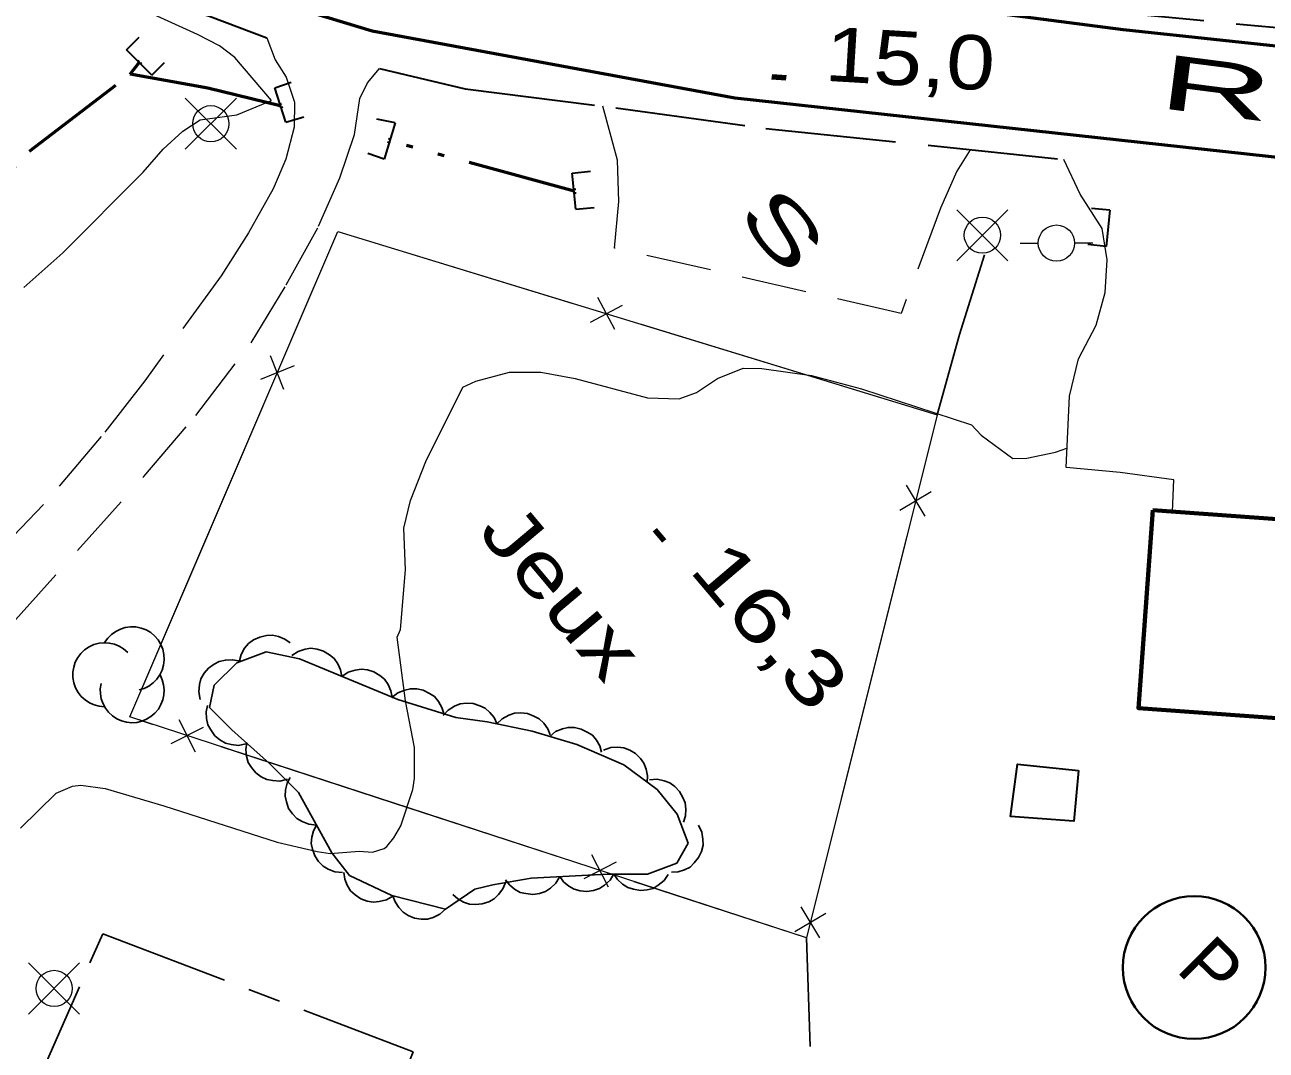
# Model space of a CAD drawing. Extents: x 386081 to 389416, y 5130568 to 5134082.
# Drawn here: x 387512.1 to 387580.7, y 5132255.4 to 5132312.1 of the extents above; entities that cross this region are included whole.
import ezdxf
from ezdxf.enums import TextEntityAlignment as Align

# ---------------------------------------------------------------- set-up
doc = ezdxf.new("R2010")
doc.units = 0
doc.header["$LTSCALE"] = 1.2
for name, pattern in [('DASH_DOUBLE_DOT', [9.2, 5, -1.2, 0.3, -1.2, 0.3, -1.2]), ('DOT_DASHED', [7.7, 5, -1.2, 0.3, -1.2]), ('LONG_DASH_SHORT_DASH', [9.9, 6, -1.2, 1.5, -1.2]), ('LONG_DASHED', [7.5, 6, -1.5]), ('MEDIUM_DASHED', [4.5, 3, -1.5])]:
    doc.linetypes.add(name, pattern=pattern)
for name, color, linetype, lineweight in [('19', 7, 'Continuous', 13), ('2', 7, 'Continuous', 13), ('21', 7, 'LONG_DASHED', 35), ('26', 7, 'Continuous', 35), ('3', 7, 'Continuous', 140), ('31', 7, 'Continuous', 70), ('36', 7, 'Continuous', 13), ('37', 7, 'Continuous', 13), ('38', 7, 'Continuous', 40), ('4', 7, 'DASH_DOUBLE_DOT', 53), ('41', 7, 'DOT_DASHED', 25), ('44', 7, 'Continuous', 25), ('52', 7, 'Continuous', 13), ('56', 7, 'LONG_DASH_SHORT_DASH', 25)]:
    doc.layers.add(name, color=color, linetype=linetype, lineweight=lineweight)

msp = doc.modelspace()

# ---------------------------------------------------------------- linework, layer by layer
at = {"layer": '19', "linetype": 'MEDIUM_DASHED'}
for points in [[(387525.46, 5132311.34), (387525.92, 5132310.13), (387526.53, 5132309.17), (387526.99, 5132307.8), (387526.97, 5132306.42), (387526.5, 5132304.65), (387525.81, 5132303), (387524.45, 5132300.57), (387522.93, 5132298.21), (387518.71, 5132292.41), (387516.31, 5132289.32), (387513.11, 5132285.57), (387509.86, 5132282.19)], [(387511.4, 5132279.01), (387518.66, 5132287.12), (387521.53, 5132290.48), (387524.59, 5132294.51), (387526.53, 5132297.7), (387528.31, 5132300.94), (387529.49, 5132303.61), (387530.29, 5132306.01), (387530.59, 5132307.99), (387531.02, 5132308.86), (387531.67, 5132309.65)]]:
    msp.add_lwpolyline(points, dxfattribs=at)
at = {"layer": '19'}
msp.add_lwpolyline([(387575.49, 5132285.19), (387575.57, 5132286.94), (387572.6, 5132287.34), (387569.61, 5132287.62), (387569.79, 5132291.55), (387570.29, 5132293.62), (387571.27, 5132295.48), (387571.77, 5132297.28), (387571.88, 5132299.08), (387571.61, 5132300.82), (387570.39, 5132302.72), (387569.49, 5132304.63)], dxfattribs=at)
at = {"layer": '2'}
for points in [[(387512.03, 5132297.55), (387514.18, 5132299.47), (387518.63, 5132303.92), (387519.72, 5132305.2), (387520.81, 5132306.2), (387521.77, 5132306.82), (387523.8, 5132307.09), (387525.71, 5132307.88), (387523.69, 5132310.26), (387522.84, 5132310.91), (387521.63, 5132311.54), (387512.31, 5132315.78)], [(387511.85, 5132267.7), (387513.81, 5132269.62), (387514.72, 5132270.01), (387515.18, 5132270.07), (387516.53, 5132269.88), (387519.77, 5132268.93), (387526.03, 5132266.93), (387528.23, 5132266.4), (387528.95, 5132266.3), (387530.56, 5132266.42), (387531.3, 5132266.37), (387531.94, 5132266.57), (387532.09, 5132266.69), (387532.48, 5132267.17), (387532.86, 5132267.82), (387533.52, 5132269.84), (387533.62, 5132270.43), (387533.61, 5132272.15), (387533.11, 5132274.72), (387532.65, 5132278.24), (387532.83, 5132278.66), (387533.12, 5132281.96), (387533.02, 5132284.26), (387533.39, 5132285.8), (387534.23, 5132287.95), (387536.29, 5132292.05), (387537, 5132292.38), (387538.87, 5132292.88), (387540.59, 5132292.88), (387542.48, 5132292.53), (387546.48, 5132291.46), (387548.23, 5132291.41), (387549.19, 5132291.75), (387550.36, 5132292.53), (387551.77, 5132293.11), (387552.81, 5132293.09), (387555.54, 5132292.7), (387558.31, 5132291.97), (387564.39, 5132289.98), (387564.92, 5132289.4), (387566.67, 5132288.12), (387567.44, 5132288.13), (387569.02, 5132288.46), (387569.66, 5132288.69)]]:
    msp.add_lwpolyline(points, dxfattribs=at)
at = {"layer": '21'}
for points in [[(387448.55, 5132347.71), (387450.3, 5132348.4), (387452.56, 5132348.87), (387454.71, 5132349.01), (387456.48, 5132348.48), (387458.74, 5132347.62), (387461.09, 5132346.33), (387475.71, 5132335.51), (387479.64, 5132332.82), (387488.41, 5132327.05), (387497.41, 5132322.26), (387505.92, 5132318.13), (387510.87, 5132316.08), (387516.12, 5132314.38), (387522.29, 5132312.55), (387525.46, 5132311.34)], [(387736.86, 5132291.57), (387733.6, 5132291.99), (387709.58, 5132295.61), (387698.35, 5132296.9), (387691.83, 5132297.26), (387677.28, 5132298.75), (387662.94, 5132300.94), (387653.62, 5132302.21), (387642.37, 5132303.91), (387632.55, 5132305.72), (387621.75, 5132307.01), (387608.95, 5132308.73), (387597.98, 5132310.12), (387586.17, 5132311.43), (387566.07, 5132313.34), (387563.16, 5132314.3), (387562.13, 5132315.42), (387561.79, 5132316.7), (387562.33, 5132318.66), (387563.51, 5132320.54), (387564.77, 5132322.24), (387565.97, 5132323.49)], [(387531.67, 5132309.65), (387536.41, 5132308.53), (387544.73, 5132307.49), (387553.03, 5132306.34), (387569.49, 5132304.63)]]:
    msp.add_lwpolyline(points, dxfattribs=at)
at = {"layer": '21', "linetype": 'Continuous', "lineweight": 53}
for points in [[(387527.13, 5132312.98), (387531.27, 5132311.74), (387551.31, 5132308.03), (387585.48, 5132304.29), (387592.5, 5132303.69), (387599.65, 5132302.96), (387616.75, 5132301.03), (387622.08, 5132300.05), (387628.01, 5132299.22), (387640.73, 5132297.17), (387655.66, 5132295.26), (387659.42, 5132294.51), (387661.63, 5132293.87), (387663.49, 5132292.45), (387665.22, 5132290.58), (387666.62, 5132288.63), (387667.3, 5132286.86), (387667.22, 5132284.79), (387663.68, 5132256.15), (387661.63, 5132241.07)], [(387562.39, 5132313.16), (387572.77, 5132311.8), (387583.77, 5132310.63), (387600.02, 5132308.74), (387614.35, 5132307.05), (387628.29, 5132305.3), (387641.74, 5132303.18), (387670.62, 5132298.94), (387720.03, 5132292.53), (387763.15, 5132287.28), (387788.03, 5132285.2)]]:
    msp.add_lwpolyline(points, dxfattribs=at)
at = {"layer": '26'}
for p, q in [((387517.71, 5132310.68), (387518.41, 5132311.38)), ((387519.11, 5132309.28), (387517.71, 5132310.68)), ((387518.34, 5132310.05), (387518.41, 5132310.12)), ((387518.48, 5132309.91), (387518.34, 5132310.05)), ((387518.48, 5132309.91), (387518.55, 5132309.98)), ((387519.11, 5132309.28), (387519.81, 5132309.98)), ((387525.9, 5132308.59), (387526.8, 5132308.89)), ((387526.5, 5132306.69), (387525.9, 5132308.59)), ((387526.17, 5132307.69), (387526.26, 5132307.72)), ((387526.23, 5132307.5), (387526.17, 5132307.69)), ((387526.23, 5132307.5), (387526.33, 5132307.53)), ((387526.5, 5132306.69), (387527.5, 5132306.99)), ((387532.54, 5132306.65), (387531.54, 5132306.85)), ((387532.54, 5132306.65), (387531.94, 5132304.65)), ((387532.21, 5132305.55), (387532.12, 5132305.58)), ((387532.27, 5132305.75), (387532.17, 5132305.77)), ((387532.27, 5132305.75), (387532.21, 5132305.55)), ((387531.94, 5132304.65), (387531.04, 5132304.95)), ((387542.33, 5132303.88), (387543.33, 5132303.98)), ((387542.53, 5132301.88), (387542.33, 5132303.88)), ((387542.42, 5132302.98), (387542.52, 5132302.99)), ((387542.44, 5132302.78), (387542.42, 5132302.98)), ((387542.44, 5132302.78), (387542.54, 5132302.79)), ((387542.53, 5132301.88), (387543.53, 5132301.98)), ((387572.02, 5132301.83), (387571.02, 5132301.93)), ((387572.02, 5132301.83), (387571.82, 5132299.83)), ((387571.82, 5132299.83), (387570.82, 5132299.93))]:
    msp.add_line(p, q, dxfattribs=at)
at = {"layer": '3'}
for p, q in [((387553.36, 5132309.19), (387554.15, 5132309.14)), ((387546.89, 5132284.17), (387547.4, 5132283.56))]:
    msp.add_line(p, q, dxfattribs=at)
at = {"layer": '31'}
msp.add_lwpolyline([(387574.41, 5132285.26), (387585.85, 5132284.43), (387585.06, 5132273.5), (387573.61, 5132274.33)], close=True, dxfattribs=at)
at = {"layer": '31', "lineweight": 35}
msp.add_lwpolyline([(387570.3, 5132270.88), (387570.03, 5132268.09), (387566.54, 5132268.34), (387566.93, 5132271.23)], close=True, dxfattribs=at)
at = {"layer": '36'}
for p, q in [((387523.77, 5132305.19), (387520.95, 5132308.01)), ((387520.95, 5132305.19), (387523.77, 5132308.01)), ((387566.39, 5132299.03), (387563.57, 5132301.85)), ((387563.57, 5132299.03), (387566.39, 5132301.85)), ((387567.08, 5132300.01), (387568.08, 5132300.01)), ((387571.08, 5132300.01), (387570.08, 5132300.01)), ((387515.11, 5132257.43), (387512.29, 5132260.25)), ((387512.29, 5132257.43), (387515.11, 5132260.25))]:
    msp.add_line(p, q, dxfattribs=at)
for centre in [(387522.364, 5132306.605), (387564.984, 5132300.445), (387569.074, 5132300.01), (387513.704, 5132258.845)]:
    msp.add_circle(centre, 1, dxfattribs=at)
at = {"layer": '37'}
for p, q in [((387532.74, 5132299.62), (387542.3, 5132296.7)), ((387543.33, 5132295.64), (387545.1, 5132296.58)), ((387544.68, 5132295.23), (387543.74, 5132297)), ((387546.13, 5132295.53), (387555.69, 5132292.61)), ((387526.4, 5132291.93), (387525.66, 5132293.79)), ((387526.96, 5132293.23), (387525.1, 5132292.48)), ((387521.31, 5132281.82), (387525.25, 5132291.02)), ((387560.43, 5132285.26), (387562.15, 5132286.29)), ((387560.78, 5132286.64), (387561.81, 5132284.92)), ((387560.81, 5132283.84), (387558.38, 5132274.13)), ((387558.38, 5132274.13), (387555.96, 5132264.43)), ((387521.93, 5132273.26), (387520.15, 5132272.36)), ((387520.59, 5132273.7), (387521.49, 5132271.92)), ((387532.45, 5132269.08), (387522.94, 5132272.19)), ((387541.95, 5132265.98), (387532.45, 5132269.08)), ((387543.4, 5132266.25), (387544.31, 5132264.46)), ((387544.75, 5132265.81), (387542.96, 5132264.9)), ((387555.26, 5132261.63), (387545.75, 5132264.74)), ((387554.62, 5132261.98), (387556.33, 5132263.01)), ((387554.96, 5132263.35), (387555.99, 5132261.63))]:
    msp.add_line(p, q, dxfattribs=at)
msp.add_lwpolyline([(387555.26, 5132261.63), (387517.89, 5132273.84), (387529.37, 5132300.65), (387562.48, 5132290.53)], close=True, dxfattribs=at)
for points in [[(387526.82, 5132294.69), (387529.37, 5132300.65), (387532.74, 5132299.62)], [(387555.69, 5132292.61), (387562.48, 5132290.53), (387561.78, 5132287.72)], [(387519.14, 5132273.43), (387517.89, 5132273.84), (387521.31, 5132281.82)]]:
    msp.add_lwpolyline(points, dxfattribs=at)
at = {"layer": '38'}
msp.add_circle((387576.686, 5132260), 3.941, dxfattribs=at)
at = {"layer": '4'}
msp.add_line((387542.43, 5132302.88), (387532.24, 5132305.65), dxfattribs=at)
for points in [[(387526.2, 5132307.59), (387522.2, 5132308.57), (387517.91, 5132309.34), (387518.41, 5132309.98)], [(387486.04, 5132262.3), (387484.84, 5132263.26), (387481.63, 5132266.45), (387480.38, 5132268.94), (387480.96, 5132271.69), (387484.1, 5132275.76), (387493.5, 5132285.18), (387505.02, 5132297.25), (387512.35, 5132305.09), (387517.91, 5132309.34)]]:
    msp.add_lwpolyline(points, dxfattribs=at)
at = {"layer": '41'}
msp.add_line((387555.26, 5132261.63), (387555.65, 5132250.78), dxfattribs=at)
msp.add_lwpolyline([(387562.48, 5132290.53), (387563.72, 5132294.96), (387565.11, 5132299.37)], dxfattribs=at)
at = {"layer": '44'}
for points in [[(387523.93, 5132276.87), (387524.03, 5132277.28), (387524.23, 5132277.63), (387524.44, 5132277.89), (387524.72, 5132278.09), (387525.06, 5132278.25), (387525.43, 5132278.33), (387525.76, 5132278.36), (387526.1, 5132278.28), (387526.45, 5132278.14), (387526.74, 5132277.93)], [(387526.83, 5132277.23), (387527.18, 5132277.46), (387527.57, 5132277.58), (387527.89, 5132277.63), (387528.24, 5132277.58), (387528.59, 5132277.47), (387528.92, 5132277.27), (387529.17, 5132277.07), (387529.37, 5132276.77), (387529.53, 5132276.44), (387529.6, 5132276.08)], [(387521.77, 5132274.81), (387521.69, 5132275.22), (387521.73, 5132275.63), (387521.81, 5132275.95), (387521.99, 5132276.25), (387522.23, 5132276.53), (387522.54, 5132276.76), (387522.83, 5132276.91), (387523.17, 5132276.98), (387523.54, 5132277), (387523.9, 5132276.93)], [(387529.6, 5132276.08), (387529.95, 5132276.32), (387530.34, 5132276.43), (387530.66, 5132276.48), (387531.01, 5132276.44), (387531.37, 5132276.33), (387531.69, 5132276.12), (387531.95, 5132275.92), (387532.15, 5132275.63), (387532.3, 5132275.29), (387532.37, 5132274.94)], [(387532.36, 5132274.91), (387532.69, 5132275.17), (387533.07, 5132275.32), (387533.39, 5132275.4), (387533.74, 5132275.39), (387534.1, 5132275.31), (387534.44, 5132275.14), (387534.72, 5132274.96), (387534.94, 5132274.69), (387535.12, 5132274.36), (387535.23, 5132274.02)], [(387524.3, 5132272.35), (387523.89, 5132272.27), (387523.49, 5132272.31), (387523.17, 5132272.39), (387522.86, 5132272.57), (387522.58, 5132272.8), (387522.36, 5132273.12), (387522.2, 5132273.4), (387522.13, 5132273.75), (387522.11, 5132274.12), (387522.18, 5132274.47)], [(387535.2, 5132273.91), (387535.48, 5132274.22), (387535.83, 5132274.43), (387536.14, 5132274.56), (387536.49, 5132274.6), (387536.86, 5132274.58), (387537.22, 5132274.46), (387537.52, 5132274.33), (387537.78, 5132274.09), (387538.01, 5132273.81), (387538.17, 5132273.48)], [(387538.17, 5132273.45), (387538.46, 5132273.74), (387538.83, 5132273.93), (387539.14, 5132274.05), (387539.49, 5132274.07), (387539.85, 5132274.03), (387540.21, 5132273.89), (387540.5, 5132273.74), (387540.75, 5132273.49), (387540.97, 5132273.19), (387541.11, 5132272.86)], [(387541.08, 5132272.76), (387541.41, 5132273.03), (387541.79, 5132273.18), (387542.1, 5132273.26), (387542.46, 5132273.25), (387542.82, 5132273.17), (387543.16, 5132273), (387543.44, 5132272.83), (387543.66, 5132272.56), (387543.85, 5132272.24), (387543.95, 5132271.89)], [(387526.59, 5132270.4), (387526.18, 5132270.3), (387525.78, 5132270.32), (387525.45, 5132270.38), (387525.14, 5132270.53), (387524.84, 5132270.76), (387524.6, 5132271.05), (387524.42, 5132271.33), (387524.33, 5132271.67), (387524.3, 5132272.04), (387524.35, 5132272.4)], [(387544.05, 5132272.01), (387544.45, 5132272.15), (387544.85, 5132272.17), (387545.18, 5132272.14), (387545.51, 5132272.01), (387545.83, 5132271.82), (387546.09, 5132271.54), (387546.29, 5132271.29), (387546.41, 5132270.96), (387546.48, 5132270.59), (387546.47, 5132270.23)], [(387528.19, 5132267.87), (387527.78, 5132267.91), (387527.4, 5132268.07), (387527.11, 5132268.23), (387526.87, 5132268.49), (387526.66, 5132268.79), (387526.54, 5132269.15), (387526.46, 5132269.47), (387526.49, 5132269.82), (387526.58, 5132270.18), (387526.75, 5132270.5)], [(387546.59, 5132270.36), (387547.01, 5132270.4), (387547.41, 5132270.31), (387547.72, 5132270.2), (387548, 5132269.99), (387548.26, 5132269.73), (387548.44, 5132269.39), (387548.57, 5132269.09), (387548.61, 5132268.74), (387548.58, 5132268.37), (387548.48, 5132268.03)], [(387529.64, 5132265.25), (387529.22, 5132265.28), (387528.84, 5132265.44), (387528.56, 5132265.6), (387528.31, 5132265.86), (387528.11, 5132266.16), (387527.98, 5132266.53), (387527.91, 5132266.84), (387527.94, 5132267.19), (387528.03, 5132267.55), (387528.19, 5132267.87)], [(387549.3, 5132267.86), (387549.49, 5132267.48), (387549.55, 5132267.08), (387549.56, 5132266.75), (387549.47, 5132266.41), (387549.31, 5132266.08), (387549.07, 5132265.78), (387548.84, 5132265.55), (387548.52, 5132265.39), (387548.17, 5132265.28), (387547.81, 5132265.26)], [(387532.42, 5132263.94), (387532.06, 5132263.73), (387531.66, 5132263.64), (387531.33, 5132263.6), (387530.99, 5132263.67), (387530.64, 5132263.8), (387530.33, 5132264.02), (387530.08, 5132264.24), (387529.9, 5132264.54), (387529.76, 5132264.88), (387529.71, 5132265.24)], [(387541.64, 5132265.02), (387541.42, 5132264.66), (387541.12, 5132264.39), (387540.85, 5132264.2), (387540.51, 5132264.09), (387540.15, 5132264.04), (387539.77, 5132264.08), (387539.45, 5132264.15), (387539.14, 5132264.33), (387538.86, 5132264.57), (387538.64, 5132264.85)], [(387544.63, 5132265.18), (387544.42, 5132264.82), (387544.11, 5132264.55), (387543.84, 5132264.36), (387543.51, 5132264.25), (387543.14, 5132264.2), (387542.76, 5132264.24), (387542.44, 5132264.32), (387542.14, 5132264.49), (387541.85, 5132264.73), (387541.64, 5132265.02)], [(387547.63, 5132265.14), (387547.4, 5132264.8), (387547.08, 5132264.55), (387546.8, 5132264.37), (387546.46, 5132264.29), (387546.09, 5132264.26), (387545.71, 5132264.32), (387545.4, 5132264.41), (387545.1, 5132264.61), (387544.83, 5132264.86), (387544.63, 5132265.16)], [(387538.65, 5132264.74), (387538.5, 5132264.35), (387538.26, 5132264.03), (387538.02, 5132263.79), (387537.71, 5132263.63), (387537.36, 5132263.51), (387536.98, 5132263.48), (387536.65, 5132263.49), (387536.32, 5132263.61), (387536, 5132263.79), (387535.73, 5132264.03)], [(387535.33, 5132263.22), (387535.02, 5132262.94), (387534.65, 5132262.77), (387534.33, 5132262.67), (387533.98, 5132262.67), (387533.62, 5132262.73), (387533.27, 5132262.88), (387532.98, 5132263.05), (387532.75, 5132263.31), (387532.54, 5132263.62), (387532.42, 5132263.95)]]:
    msp.add_lwpolyline(points, dxfattribs=at)
at = {"layer": '44', "linetype": 'DOT_DASHED'}
msp.add_lwpolyline([(387535.33, 5132263.22), (387532.36, 5132263.97), (387530.02, 5132265.09), (387529.04, 5132266.33), (387527.21, 5132269.66), (387525.61, 5132271.27), (387523.52, 5132273.13), (387522.29, 5132274.36), (387522.55, 5132275.59), (387523.79, 5132276.82), (387525.41, 5132277.43), (387527.26, 5132277.05), (387532.69, 5132274.81), (387535.9, 5132273.81), (387537.63, 5132273.56), (387540.11, 5132273.06), (387542.58, 5132272.31), (387545.17, 5132271.19), (387547.02, 5132269.83), (387548.12, 5132268.47), (387548.73, 5132266.86), (387548.1, 5132265.76), (387546.49, 5132265.15), (387544.26, 5132265.16), (387540.05, 5132264.93), (387537.94, 5132264.57), (387536.95, 5132264.33)], close=True, dxfattribs=at)
at = {"layer": '44'}
for centre, start, end in [((387518.018, 5132277.053), 282.26917, 149.72626), ((387516.499, 5132276.17), 44.11537, 269.80396), ((387518.018, 5132275.287), 166.93686, 29.62122)]:
    msp.add_arc(centre, 1.766, start, end, dxfattribs=at)
at = {"layer": '52', "linetype": 'MEDIUM_DASHED'}
msp.add_lwpolyline([(387564.31, 5132305.16), (387563.58, 5132303.99), (387562.68, 5132301.94), (387560.49, 5132296.13), (387544.66, 5132299.73), (387544.91, 5132302.3), (387544.82, 5132304.59), (387544.02, 5132307.58)], dxfattribs=at)
at = {"layer": '56'}
msp.add_lwpolyline([(387516.39, 5132261.86), (387533.54, 5132255.34), (387520.72, 5132223.4), (387502.61, 5132230.61)], close=True, dxfattribs=at)

# ---------------------------------------------------------------- texts
at = {"layer": '21', "width": 2.15}
msp.add_text('RUE MIKOWA', height=3, rotation=352.67, dxfattribs=at).set_placement((387574.62, 5132307.49))
at = {"layer": '3'}
for s, rotation, width, p in [('15,0   ', 356.584, 1.2, (387556.23, 5132308.98)), ('16,3   ', 310.294, 1.35, (387548.72, 5132281.95))]:
    msp.add_text(s, height=3, rotation=rotation, dxfattribs=dict(at, width=width)).set_placement(p)
at = {"layer": '38'}
msp.add_text('P', height=3, rotation=315.272, dxfattribs=at).set_placement((387575.62, 5132259.83))
at = {"layer": '52', "width": 1.7}
msp.add_text('S', height=3, rotation=310.03, dxfattribs=at).set_placement((387551.36, 5132301.54))
at = {"layer": '56', "width": 1.3}
msp.add_text('Jeux', height=3, rotation=310.03, dxfattribs=at).set_placement((387540.599, 5132279.815), align=Align.CENTER)

doc.saveas('drawing.dxf')
